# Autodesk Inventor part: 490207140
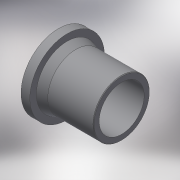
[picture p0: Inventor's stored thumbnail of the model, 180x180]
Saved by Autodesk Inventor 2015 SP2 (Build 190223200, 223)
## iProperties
Created: 2017-07
Part Number: 490207140
Material: Generic
Description: Stub Flange 140
Document SubType Name: Modeling
Designer: Кирилл
Mass: 1343.86 g
Surface Area: 1829.68 cm^2
Volume: 1343.86 cm^3
Density: 1 g/cm^3
Appearance: Default
Author: Кирилл
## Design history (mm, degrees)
derived "490207.ipt"
feature "Solid1::490207.ipt"
tag "TaggingFeature1"
body "Solid1"
other parameters: "d1" = 155, "d3" = 112, "d4" = 188, "d5" = 25, "d17" = 2.8, "d18" = 2.8, "d19" = 2.8, "d21" = 2.8, "d24" = 2.8, "d25" = 2.8, "d26" = 1.4, "d27" = 0, "d32" = 1.4, "D_" = 188, "D_1" = 155, "a_" = 25
